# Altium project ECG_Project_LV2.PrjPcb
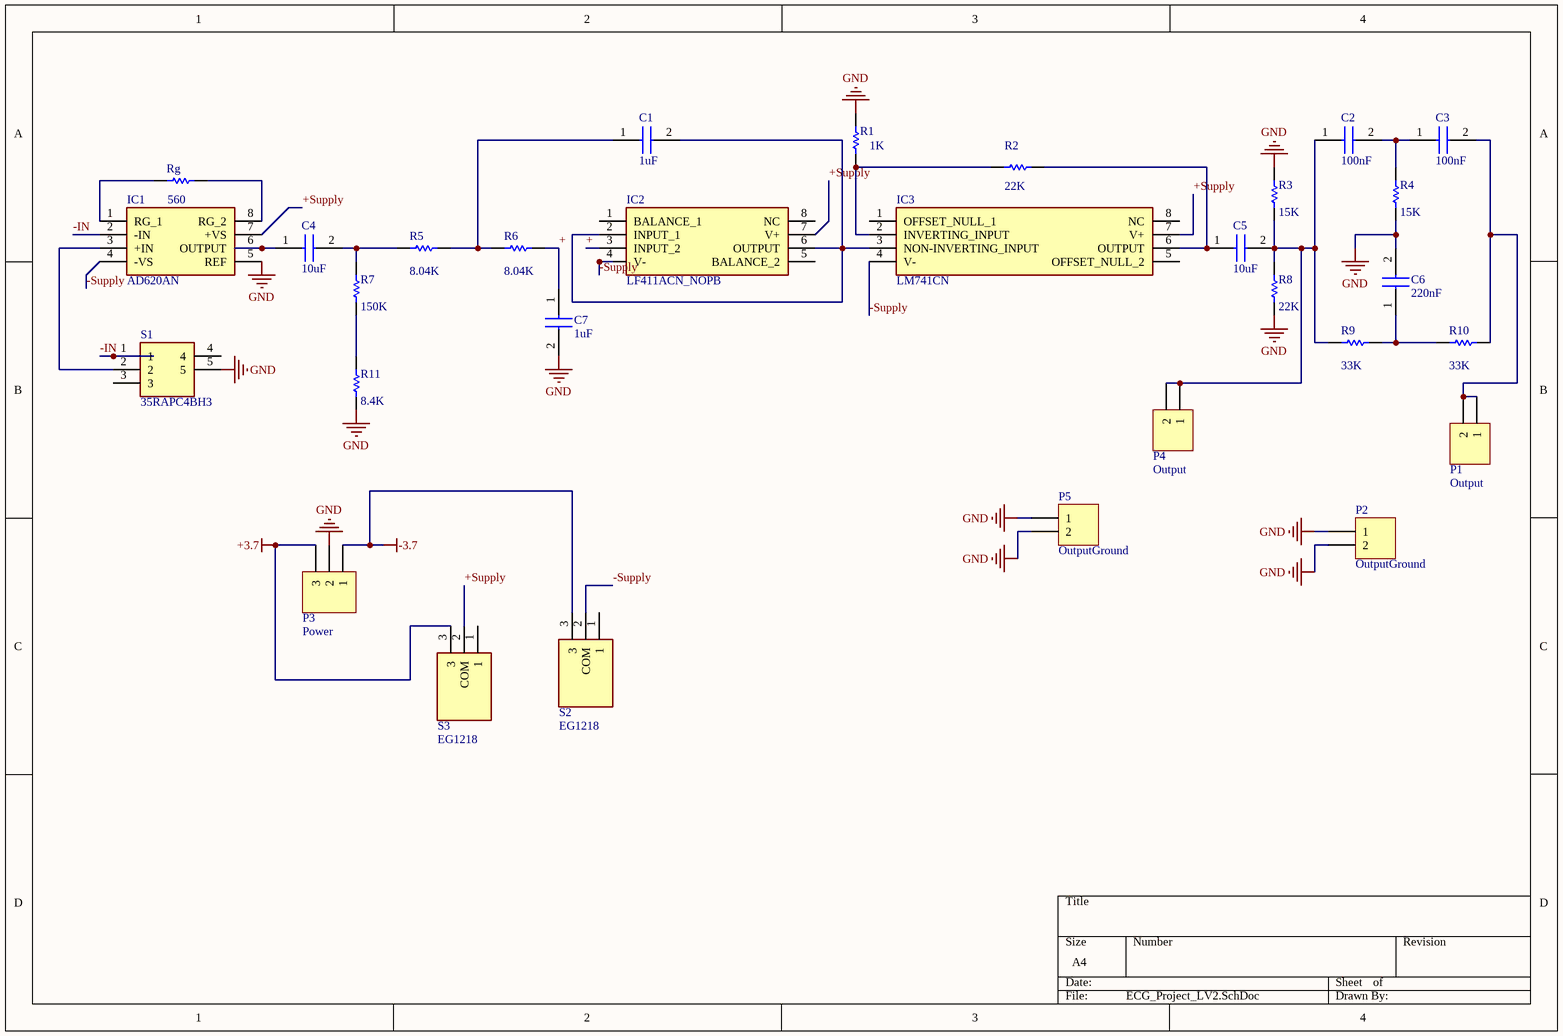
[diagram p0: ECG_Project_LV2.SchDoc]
1 sheet, 30 parts. Net scope: global (net labels, ports and power ports of the same name join across sheets).
Board file: ECG_Project_LV2.PcbDoc

## Sheet ECG_Project_LV2.SchDoc
size A4

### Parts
C1  1uF  [TAP106K016GSB]
C2  100nF  [TAP106K016GSB]
C3  100nF  [TAP106K016GSB]
C4  10uF  [TAP106K016GSB]
C5  10uF  [TAP106K016GSB]
C6  220nF  [TAP106K016GSB]
C7  1uF  [TAP106K016GSB]
IC1  AD620AN  [DIP794W56P254L959H533Q8N]
IC2  LF411ACN_NOPB  [DIP794W53P254L959H508Q8N]
IC3  LM741CN  [DIP794W53P254L959H508Q8N]
P1  Output  [HDR1X2]
P2  OutputGround  [HDR1X2]
P3  Power  [HDR1X3]
P4  Output  [HDR1X2]
P5  OutputGround  [HDR1X2]
R1  value 1K  [AXIAL-0.3]  (hidden comment: Res1)
R2  value 22K  [AXIAL-0.3]  (hidden comment: Res1)
R3  value 15K  [AXIAL-0.3]  (hidden comment: Res1)
R4  value 15K  [AXIAL-0.3]  (hidden comment: Res1)
R5  value 8.04K  [AXIAL-0.3]  (hidden comment: Res1)
R6  value 8.04K  [AXIAL-0.3]  (hidden comment: Res1)
R7  value 150K  [AXIAL-0.3]  (hidden comment: Res1)
R8  value 22K  [AXIAL-0.3]  (hidden comment: Res1)
R9  value 33K  [AXIAL-0.3]  (hidden comment: Res1)
R10  value 33K  [AXIAL-0.3]  (hidden comment: Res1)
R11  value 8.4K  [AXIAL-0.3]  (hidden comment: Res1)
Rg  value 560  [AXIAL-0.3]  (hidden comment: Res1)
S1  35RAPC4BH3  [35RAPC4BH3]
S2  EG1218  [3PIN_SLIDE_SWITCH]
S3  EG1218  [3PIN_SLIDE_SWITCH]

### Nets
+3.7: P3.3 S3.3
-3.7: P3.1 S2.3
GND: C6.2(A) C7.2(A) IC1.5(REF) P2.1 P2.2 P3.2 P5.1 P5.2 R1.2 R3.2 R4.1 R8.1 R11.1 S1.5
+: C7.1(K) IC2.3(INPUT_2) R6.2
+Supply: IC1.7(+VS) IC2.7(V+) IC3.7(V+) S3.2(COM)
-IN: IC1.2(-IN) S1.1
-Supply: IC1.4(-VS) IC2.4(V-) IC3.4(V-) S2.2(COM)
NetC1_1: C1.1(K) R5.2 R6.1
NetC1_2: C1.2(A) IC2.2(INPUT_1) IC2.6(OUTPUT) IC3.3(NON-INVERTING_INPUT)
NetC2_1: C2.1(K) C5.2(A) P4.1 P4.2 R3.1 R8.2 R9.1
NetC2_2: C2.2(A) C3.1(K) R4.2
NetC3_2: C3.2(A) P1.1 P1.2 R10.2
NetC4_1: C4.1(K) IC1.6(OUTPUT)
NetC4_2: C4.2(A) R5.1 R7.2
NetC5_1: C5.1(K) IC3.6(OUTPUT) R2.2
NetC6_1: C6.1(K) R9.2 R10.1
NetIC1_1: IC1.1(RG_1) Rg.1
NetIC1_3: IC1.3(+IN) S1.2
NetIC1_8: IC1.8(RG_2) Rg.2
NetIC3_2: IC3.2(INVERTING_INPUT) R1.1 R2.1
NetR7_1: R7.1 R11.2

Not connected (* = marked no-connect by the designer): IC2 1(BALANCE_1) 5(BALANCE_2) 8(NC); IC3 1(OFFSET_NULL_1) 5(OFFSET_NULL_2) 8(NC); S1 3 4; S2 1; S3 1

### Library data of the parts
C1-C7 = TAP106K016GSB: Capacitor; Manufacturer_Name: AVX
IC1 = AD620AN: Integrated Circuit; Manufacturer_Name: Analog Devices
IC2 = LF411ACN_NOPB: Integrated Circuit; Manufacturer_Name: Texas Instruments; Manufacturer_Part_Number: LF411ACN/NOPB
IC3 = LM741CN: Integrated Circuit; Manufacturer_Name: Texas Instruments
P1 P2 P4 P5 = Header 2: Header, 2-Pin
P3 = Header 3: Header, 3-Pin
R1-R11 Rg = Res1: Resistor
S1 = 35RAPC4BH3: Switch; Manufacturer_Name: Switchcraft; Allied_Number: 70214416
S2 S3 = EG1218: Switch; Manufacturer_Name: E-Switch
